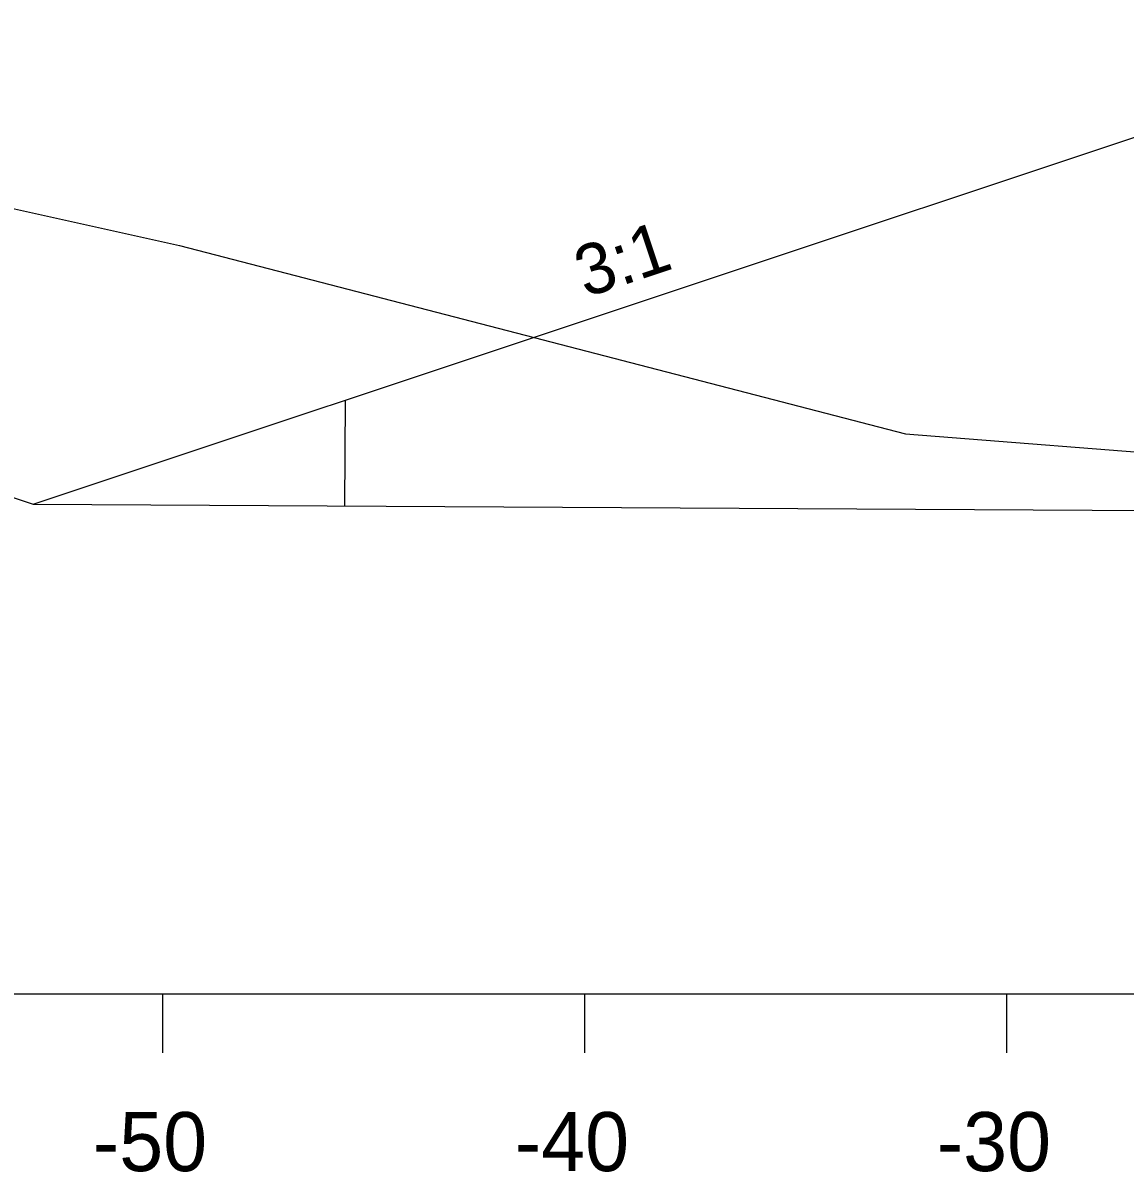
# Model space of a CAD drawing. Extents: x 2829243 to 2838161, y 467639 to 474695.
# Drawn here: x 2831905.4 to 2832036, y 469949.2 to 470085.3 of the extents above; entities that cross this region are included whole.
import ezdxf

# ---------------------------------------------------------------- set-up
doc = ezdxf.new("R2010")
doc.units = 0
for name, color, linetype in [('R_Axis', 7, 'Continuous'), ('R_Axis Annot', 7, 'Continuous'), ('R_Exist Surface', 7, 'Continuous'), ('R_Fin Surface', 7, 'Continuous'), ('R_Water', 7, 'Continuous'), ('R_Xsect Slope', 7, 'Continuous')]:
    doc.layers.add(name, color=color, linetype=linetype)

msp = doc.modelspace()

# ---------------------------------------------------------------- linework, layer by layer
at = {"layer": 'R_Axis'}
for p, q in [((2831421.96, 469970.29), (2832921.96, 469970.29)), ((2831921.96, 469963.29), (2831921.96, 469970.29)), ((2831971.96, 469963.29), (2831971.96, 469970.29)), ((2832021.96, 469963.29), (2832021.96, 469970.29))]:
    msp.add_line(p, q, dxfattribs=at)
at = {"layer": 'R_Exist Surface'}
msp.add_lwpolyline([(2831891.2, 470066.21), (2831923.92, 470058.94), (2832009.96, 470036.62), (2832045.14, 470033.88), (2832075.41, 470031.51), (2832093.85, 470029.19), (2832165.67, 470027.94), (2832167.32, 470027.92), (2832170.89, 470027.85), (2832240.25, 470032.54), (2832255.72, 470032.55), (2832282.38, 470035.38), (2832330.03, 470037.9), (2832343.03, 470037.95), (2832345.71, 470038), (2832355.82, 470041.63), (2832425.43, 470055.06), (2832491.03, 470069.51), (2832499.96, 470071.51), (2832513.84, 470074.54), (2832570.91, 470076.45)], dxfattribs=at)
at = {"layer": 'R_Fin Surface'}
msp.add_lwpolyline([(2831789.07, 470067.46), (2831789.07, 470067.45), (2831906.59, 470028.29), (2832046.96, 470075.08), (2832062.75, 470077.71), (2832096.96, 470083.41), (2832116.96, 470084.21), (2832165.15, 470085.17), (2832171.96, 470085.31), (2832179.86, 470085.15), (2832226.96, 470084.21), (2832237.43, 470083.79), (2832246.96, 470083.41), (2832281.16, 470077.71), (2832311.96, 470072.58), (2832389.58, 470071.03)], dxfattribs=at)
at = {"layer": 'R_Water'}
for p, q in [((2831943.52, 470028.08), (2831943.59, 470040.62)), ((2831906.59, 470028.29), (2832271.96, 470026.23))]:
    msp.add_line(p, q, dxfattribs=at)

# ---------------------------------------------------------------- texts
at = {"layer": 'R_Axis Annot'}
for s, p in [('-50', (2831913.67, 469949.29)), ('-40', (2831963.67, 469949.29)), ('-30', (2832013.67, 469949.29))]:
    msp.add_text(s, height=7, dxfattribs=at).set_placement(p)
at = {"layer": 'R_Xsect Slope'}
msp.add_text('3:1', height=6, rotation=18.4339, dxfattribs=at).set_placement((2831972.04, 470052.74))

doc.saveas('drawing.dxf')
